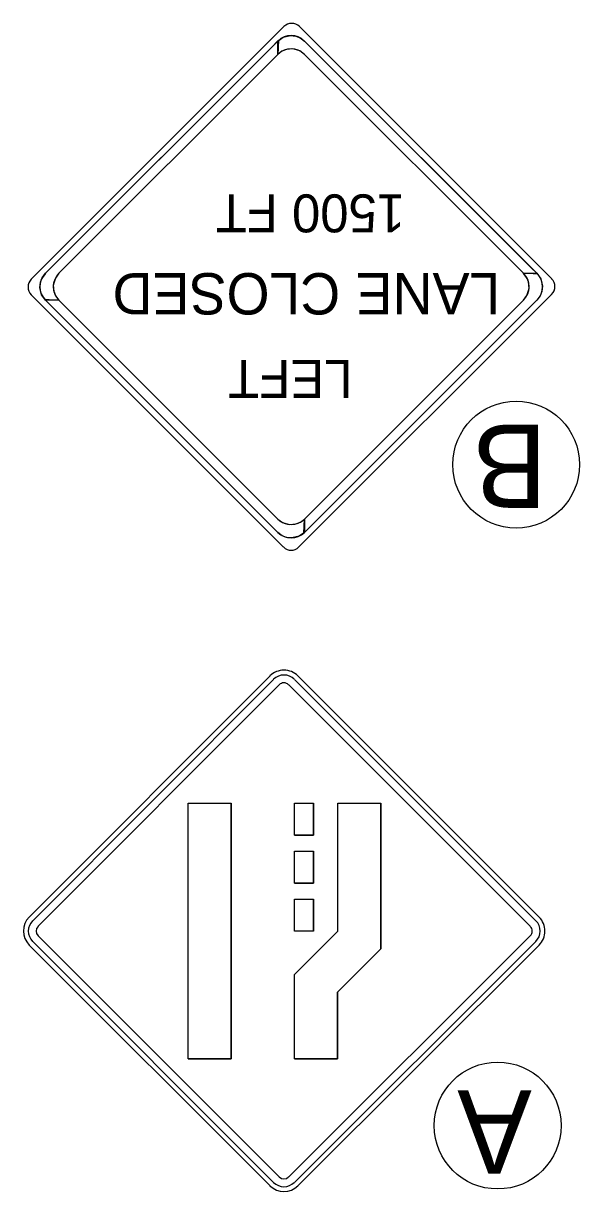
# Model space of a CAD drawing. Extents: x 1531.5 to 1538.6, y 1529.6 to 1539.6.
# Drawn here: x 1533.96 to 1534.691, y 1534.333 to 1535.869 of the extents above; entities that cross this region are included whole.
import ezdxf

# ---------------------------------------------------------------- set-up
doc = ezdxf.new("R2010")
doc.units = 0
doc.layers.add('DETL-LINE', color=7, linetype='Continuous')

msp = doc.modelspace()

# ---------------------------------------------------------------- linework, layer by layer
at = {"layer": 'DETL-LINE'}
for p, q in [((1534.3022, 1535.8651), (1533.97, 1535.5329)), ((1534.6542, 1535.5336), (1534.3228, 1535.8651)), ((1533.9886, 1535.5407), (1534.2941, 1535.8461)), ((1534.3294, 1535.8461), (1534.6348, 1535.5407)), ((1534.2941, 1535.8285), (1534.0062, 1535.5407)), ((1534.6172, 1535.5407), (1534.3293, 1535.8285)), ((1533.97, 1535.5123), (1534.3014, 1535.1809)), ((1534.2941, 1535.1999), (1533.9886, 1535.5054)), ((1534.0062, 1535.5054), (1534.2941, 1535.2175)), ((1534.322, 1535.1809), (1534.6542, 1535.5131)), ((1534.6348, 1535.5054), (1534.3294, 1535.1999)), ((1534.3294, 1535.2175), (1534.6172, 1535.5054)), ((1534.2839, 1535.0114), (1533.9672, 1534.6941)), ((1534.6379, 1534.6941), (1534.3205, 1535.0114)), ((1534.2885, 1535.0068), (1533.9719, 1534.6894)), ((1534.2959, 1534.9994), (1533.9792, 1534.6821)), ((1534.6259, 1534.6821), (1534.3085, 1534.9994)), ((1534.6332, 1534.6894), (1534.3159, 1535.0068)), ((1534.1762, 1534.5077), (1534.1762, 1534.8438)), ((1534.1762, 1534.8438), (1534.2327, 1534.8438)), ((1534.1762, 1534.8438), (1534.2327, 1534.8438)), ((1534.1762, 1534.5077), (1534.1762, 1534.8438)), ((1534.2327, 1534.5077), (1534.2327, 1534.8438)), ((1534.2327, 1534.8438), (1534.2327, 1534.5077)), ((1534.316, 1534.8438), (1534.341, 1534.8438)), ((1534.316, 1534.8018), (1534.316, 1534.8438)), ((1534.316, 1534.8438), (1534.341, 1534.8438)), ((1534.316, 1534.8018), (1534.316, 1534.8438)), ((1534.341, 1534.8018), (1534.341, 1534.8438)), ((1534.341, 1534.8438), (1534.341, 1534.8018)), ((1534.3731, 1534.6758), (1534.3731, 1534.8438)), ((1534.3731, 1534.8438), (1534.4296, 1534.8438)), ((1534.3731, 1534.8438), (1534.4296, 1534.8438)), ((1534.3731, 1534.6758), (1534.3731, 1534.8438)), ((1534.4296, 1534.6524), (1534.4296, 1534.8438)), ((1534.4296, 1534.8438), (1534.4296, 1534.6524)), ((1534.316, 1534.8018), (1534.341, 1534.8018)), ((1534.341, 1534.8018), (1534.316, 1534.8018)), ((1534.316, 1534.7808), (1534.341, 1534.7808)), ((1534.316, 1534.7388), (1534.316, 1534.7808)), ((1534.316, 1534.7808), (1534.341, 1534.7808)), ((1534.316, 1534.7388), (1534.316, 1534.7808)), ((1534.341, 1534.7388), (1534.341, 1534.7808)), ((1534.341, 1534.7808), (1534.341, 1534.7388)), ((1534.316, 1534.7388), (1534.341, 1534.7388)), ((1534.341, 1534.7388), (1534.316, 1534.7388)), ((1534.316, 1534.7178), (1534.341, 1534.7178)), ((1534.316, 1534.6758), (1534.316, 1534.7178)), ((1534.316, 1534.7178), (1534.341, 1534.7178)), ((1534.316, 1534.6758), (1534.316, 1534.7178)), ((1534.341, 1534.6758), (1534.341, 1534.7178)), ((1534.341, 1534.7178), (1534.341, 1534.6758)), ((1534.3731, 1534.6758), (1534.316, 1534.6186)), ((1534.316, 1534.6186), (1534.3731, 1534.6758)), ((1534.341, 1534.6758), (1534.316, 1534.6758)), ((1533.9672, 1534.6574), (1534.2839, 1534.3408)), ((1533.9719, 1534.6621), (1534.2885, 1534.3454)), ((1533.9792, 1534.6694), (1534.2959, 1534.3528)), ((1534.3085, 1534.3528), (1534.6259, 1534.6694)), ((1534.3159, 1534.3454), (1534.6332, 1534.6621)), ((1534.3205, 1534.3408), (1534.6379, 1534.6574)), ((1534.4296, 1534.6524), (1534.3725, 1534.5953)), ((1534.4296, 1534.6524), (1534.3725, 1534.5953)), ((1534.316, 1534.5077), (1534.316, 1534.6186)), ((1534.316, 1534.5077), (1534.316, 1534.6186)), ((1534.3725, 1534.5077), (1534.3725, 1534.5953)), ((1534.3725, 1534.5953), (1534.3725, 1534.5077)), ((1534.1762, 1534.5077), (1534.2327, 1534.5077)), ((1534.2327, 1534.5077), (1534.1762, 1534.5077)), ((1534.316, 1534.5077), (1534.3725, 1534.5077)), ((1534.3725, 1534.5077), (1534.316, 1534.5077))]:
    msp.add_line(p, q, dxfattribs=at)
for points in [[(1533.9886, 1535.5407), (1534.2853, 1535.8373), (1534.2952, 1535.8471), (1534.2941, 1535.8285), (1534.0062, 1535.5407), (1534.0017, 1535.5345), (1533.999, 1535.5253), (1533.9998, 1535.5168), (1534.002, 1535.511), (1534.0062, 1535.5054), (1533.9886, 1535.5054), (1533.9836, 1535.5126), (1533.9814, 1535.5221), (1533.9821, 1535.5291), (1533.9844, 1535.5349)], [(1534.3293, 1535.8461), (1534.6259, 1535.5494), (1534.6358, 1535.5395), (1534.6172, 1535.5407), (1534.3294, 1535.8285), (1534.3231, 1535.8331), (1534.3139, 1535.8357), (1534.3054, 1535.835), (1534.2996, 1535.8327), (1534.2941, 1535.8285), (1534.2941, 1535.8461), (1534.3012, 1535.8511), (1534.3108, 1535.8534), (1534.3178, 1535.8526), (1534.3236, 1535.8504)], [(1534.6348, 1535.5054), (1534.3381, 1535.2088), (1534.3282, 1535.1989), (1534.3293, 1535.2175), (1534.6172, 1535.5054), (1534.6217, 1535.5116), (1534.6244, 1535.5208), (1534.6236, 1535.5293), (1534.6214, 1535.5351), (1534.6172, 1535.5407), (1534.6348, 1535.5407), (1534.6398, 1535.5335), (1534.642, 1535.5239), (1534.6413, 1535.5169), (1534.639, 1535.5111)], [(1534.2941, 1535.2), (1533.9974, 1535.4967), (1533.9876, 1535.5065), (1534.0062, 1535.5054), (1534.294, 1535.2175), (1534.3003, 1535.213), (1534.3095, 1535.2104), (1534.3179, 1535.2111), (1534.3238, 1535.2134), (1534.3293, 1535.2175), (1534.3293, 1535.2), (1534.3222, 1535.195), (1534.3126, 1535.1927), (1534.3056, 1535.1934), (1534.2998, 1535.1957)]]:
    msp.add_lwpolyline(points, close=True, dxfattribs=at)
for centre in [(1534.6075, 1535.2892), (1534.5832, 1534.4201)]:
    msp.add_circle(centre, 0.0834, dxfattribs=at)
for centre, radius, start, end in [((1534.3125, 1535.8548), 0.0145, 45, 135), ((1534.3117, 1535.8285), 0.0249, 45, 135), ((1534.3117, 1535.8109), 0.0249, 45, 135), ((1533.9803, 1535.5226), 0.0145, 135, 225), ((1534.0063, 1535.523), 0.0249, 135, 225), ((1534.0239, 1535.5231), 0.0249, 135, 225), ((1534.5996, 1535.523), 0.0249, 315, 45), ((1534.6172, 1535.523), 0.0249, 315, 45), ((1534.6439, 1535.5233), 0.0145, 315, 45), ((1534.3117, 1535.2352), 0.0249, 225, 315), ((1534.3117, 1535.2176), 0.0249, 225, 315), ((1534.3117, 1535.1911), 0.0145, 225, 315), ((1534.3022, 1534.9929), 0.026, 45, 135.06), ((1534.3022, 1534.9933), 0.0192, 45, 135.06), ((1534.3022, 1534.9935), 0.00868, 45, 135.06), ((1533.9857, 1534.6758), 0.026, 135.0601, 225), ((1533.9853, 1534.6758), 0.0192, 135.0601, 225), ((1534.6198, 1534.6758), 0.0192, 314.9399, 45), ((1534.6194, 1534.6758), 0.026, 314.9399, 45), ((1533.9851, 1534.6758), 0.00868, 135.0601, 225), ((1534.6199, 1534.6758), 0.00868, 314.9399, 45), ((1534.3022, 1534.3587), 0.00868, 225, 314.94), ((1534.3022, 1534.3593), 0.026, 225, 314.94), ((1534.3022, 1534.3589), 0.0192, 225, 314.94)]:
    msp.add_arc(centre, radius, start, end, dxfattribs=at)

# ---------------------------------------------------------------- texts
for s, height, p in [('1500 FT', 0.04995, (1534.4614, 1535.6445)), ('LANE CLOSED', 0.054433, (1534.5867, 1535.541)), ('LEFT', 0.05003, (1534.3925, 1535.4268)), ('B', 0.1095, (1534.648, 1535.3417)), ('A', 0.1095, (1534.6279, 1534.4663))]:
    msp.add_text(s, height=height, rotation=180, dxfattribs=at).set_placement(p)

doc.saveas('drawing.dxf')
